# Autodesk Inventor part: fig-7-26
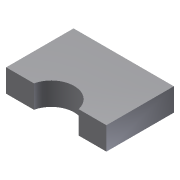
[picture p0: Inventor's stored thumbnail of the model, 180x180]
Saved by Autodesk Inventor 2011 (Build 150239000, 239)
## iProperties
Created: 2005-04
Part Number: fig-7-26
Document SubType Name: Modeling
Designer: CADCIM
Density: 1 g/cm^3
Author: CADCIM
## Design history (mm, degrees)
sketch "Sketch1"
  geometry: L1 (9.851, -16.047)-(9.851, -1.297); L2 (9.851, -1.297)-(-12.082, -1.297); L3 (-12.082, -1.297)-(-12.082, -16.047); L4 (-12.082, -16.047)-(9.851, -16.047)
  constraints: 8 end point, 2 parallel, 1 perpendicular, 1 vertical
extrude "Extrusion1" new body sketch "Sketch1" distance "d0" = 5; taper "d1" = 0 deg
sketch "Sketch2"
  geometry: C1 r 5 at (-1.115, -17.135); 1 further point
  constraints: 1 centre point
  dimensions: "d7" = 10.96654 horizontal distance of point (-12.082, -16.047) C1.centre; "d8" = 10 diameter of C1
extrude "Extrusion2" cut sketch "Sketch2" stored distance "d2" = 5; taper "d3" = 0 deg
body "Solid1"
